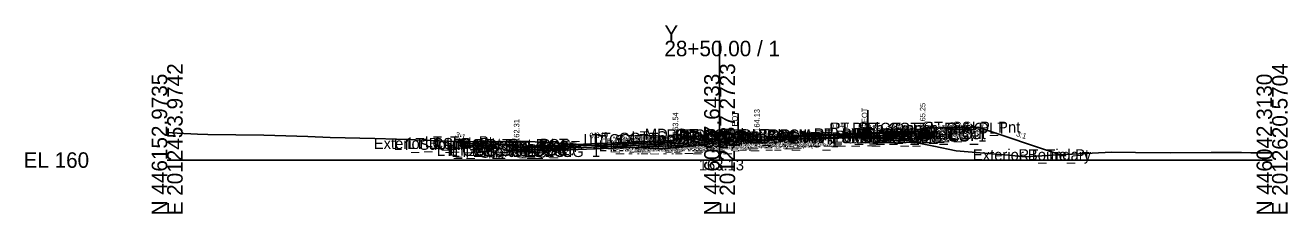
# Model space of a CAD drawing. Extents: x -26 to 3203, y -10 to 9532.
# Drawn here: x 1974.3 to 2202.8, y 2490.3 to 2524.4 of the extents above; entities that cross this region are included whole.
import ezdxf

# ---------------------------------------------------------------- set-up
doc = ezdxf.new("R2010")
doc.units = 0
for name, color, linetype in [('Default', 7, 'Continuous'), ('Exist CMT Pavement', 7, 'Continuous'), ('Exist Cross Section Cell', 7, 'Continuous'), ('Exist XS Center Line Elevation Label', 7, 'Continuous'), ('Exist XS Ground Line', 7, 'Continuous'), ('Prop CMT Conc Surface', 7, 'Continuous'), ('Prop CMT Concrete Structures', 7, 'Continuous'), ('Prop CMT Pvmt Course 1', 7, 'Continuous'), ('Prop CMT Pvmt Course 1 CG', 7, 'Continuous'), ('Prop CMT Pvmt Course 2', 7, 'Continuous'), ('Prop CMT Pvmt Course 2 Wedge', 7, 'Continuous'), ('Prop CMT Pvmt Course 3', 7, 'Continuous'), ('Prop CMT Pvmt Course 3 Wedge', 7, 'Continuous'), ('Prop CMT Pvmt Surface', 7, 'Continuous'), ('Prop CMT Slope Grass', 7, 'Continuous'), ('Prop CMT Subgrade Earthwork', 7, 'Continuous'), ('Prop XS Hydro Elevations', 7, 'Continuous'), ('Prop XS Label Text', 7, 'Continuous'), ('Prop XS SE Text', 7, 'Continuous'), ('Prop XS Side Slope Text', 7, 'Continuous'), ('Scratch_Level_0', 7, 'Continuous')]:
    doc.layers.add(name, color=color, linetype=linetype)

msp = doc.modelspace()

# ---------------------------------------------------------------- linework, layer by layer
at = {"layer": 'Exist CMT Pavement'}
msp.add_lwpolyline([(2103.35, 2503.42), (2103.35, 2503.42), (2104.94, 2503.48), (2105.71, 2503.51), (2107.81, 2503.59), (2109.14, 2503.64), (2111.71, 2503.73), (2112.49, 2503.75), (2113.7, 2503.79), (2114.54, 2503.83), (2115.17, 2503.85), (2117, 2503.89), (2117.68, 2503.9), (2118.22, 2503.92), (2120.67, 2503.97), (2121.48, 2503.99), (2122.74, 2504), (2123.31, 2504), (2123.68, 2504), (2125.46, 2504.03), (2126.84, 2504.04), (2126.84, 2504.04)], dxfattribs=at)
at = {"layer": 'Exist Cross Section Cell'}
for p, q in [((2100, 2500), (2100, 2521.56)), ((2000, 2500), (2100, 2500)), ((2100, 2500), (2200, 2500))]:
    msp.add_line(p, q, dxfattribs=at)
at = {"layer": 'Exist XS Ground Line'}
msp.add_lwpolyline([(2000, 2504.96), (2001.81, 2504.87), (2005.51, 2504.69), (2007.38, 2504.64), (2017.52, 2504.51), (2025.46, 2504.25), (2029.52, 2504.09), (2037.57, 2503.88), (2041.53, 2503.75), (2043.53, 2503.7), (2053.54, 2503.3), (2061.61, 2503.35), (2063.97, 2503.42), (2065.64, 2503.33), (2078.38, 2502.6), (2088.26, 2502.08), (2089.3, 2502.01), (2089.76, 2502.05), (2095.32, 2502.6), (2095.88, 2502.67), (2100, 2503.13), (2101.95, 2503.35), (2103.35, 2503.42), (2104.94, 2503.48), (2105.71, 2503.51), (2107.81, 2503.59), (2109.14, 2503.64), (2111.71, 2503.73), (2112.49, 2503.75), (2113.7, 2503.79), (2114.54, 2503.83), (2115.17, 2503.85), (2117, 2503.89), (2117.68, 2503.9), (2118.22, 2503.92), (2120.67, 2503.97), (2121.48, 2503.99), (2122.74, 2504), (2123.31, 2504), (2123.68, 2504), (2125.46, 2504.03), (2126.84, 2504.04), (2127.78, 2504.02), (2130.26, 2503.94), (2132.22, 2503.84), (2138.76, 2502.5), (2142.83, 2501.69), (2152.28, 2500.89), (2155.37, 2500.61), (2160.23, 2500.88), (2171.01, 2501.45), (2175.28, 2501.36), (2181.56, 2501.28), (2188.99, 2501.37), (2194.48, 2501.34), (2196.18, 2501.32), (2200, 2501.29)], dxfattribs=at)
at = {"layer": 'Prop CMT Conc Surface'}
for points in [[(2134.75, 2505.25), (2136.75, 2505.25)], [(2136.75, 2505.25), (2136.75, 2505.75), (2137.25, 2505.75)], [(2141.25, 2505.84), (2146.25, 2505.94)], [(2058.75, 2502.9), (2053.75, 2503)], [(2063.25, 2502.31), (2063.25, 2502.81), (2062.75, 2502.81)], [(2065.25, 2502.47), (2063.25, 2502.31)], [(2091.25, 2503.51), (2092, 2503.54), (2092, 2503.7), (2092.76, 2503.95)], [(2108.75, 2504.21), (2106.75, 2504.13), (2106.75, 2504.29), (2106, 2504.54)]]:
    msp.add_lwpolyline(points, dxfattribs=at)
at = {"layer": 'Prop CMT Concrete Structures'}
for points in [[(2134.75, 2505.25), (2136.75, 2505.25), (2136.75, 2505.75), (2137.25, 2505.75)], [(2137.25, 2505.75), (2137.25, 2504.76), (2134.75, 2504.66)], [(2134.75, 2504.66), (2134.75, 2505.25)], [(2146.25, 2505.94), (2141.25, 2505.84)], [(2141.25, 2505.84), (2141.25, 2505.5)], [(2141.25, 2505.5), (2146.25, 2505.6)], [(2146.25, 2505.6), (2146.25, 2505.94)], [(2053.75, 2502.66), (2053.75, 2503)], [(2053.75, 2503), (2058.75, 2502.9)], [(2058.75, 2502.56), (2053.75, 2502.66)], [(2058.75, 2502.9), (2058.75, 2502.56)], [(2065.25, 2502.47), (2063.25, 2502.31), (2063.25, 2502.81), (2062.75, 2502.81)], [(2062.75, 2502.81), (2062.75, 2501.78), (2065.25, 2501.88)], [(2065.25, 2501.88), (2065.25, 2502.47)], [(2091.25, 2503.51), (2092, 2503.54), (2092, 2503.7), (2092.76, 2503.95)], [(2091.25, 2502.92), (2091.25, 2503.51)], [(2092.76, 2502.98), (2091.25, 2502.92)], [(2092.76, 2503.95), (2092.76, 2502.98)], [(2108.75, 2504.21), (2106.75, 2504.13), (2106.75, 2504.29), (2106, 2504.54)], [(2106, 2504.54), (2106, 2503.51)], [(2106, 2503.51), (2108.75, 2503.62)], [(2108.75, 2503.62), (2108.75, 2504.21)]]:
    msp.add_lwpolyline(points, dxfattribs=at)
at = {"layer": 'Prop CMT Pvmt Course 1'}
for points in [[(2108.75, 2504.21), (2134.75, 2505.25)], [(2134.75, 2505), (2127.78, 2504.72), (2108.75, 2503.96)], [(2134.75, 2505.25), (2134.75, 2505)], [(2091.25, 2503.51), (2065.25, 2502.47)], [(2065.25, 2502.22), (2091.25, 2503.26)], [(2065.25, 2502.47), (2065.25, 2502.22)], [(2091.25, 2503.26), (2091.25, 2503.51)], [(2091.25, 2503.26), (2091.25, 2503.26), (2091.25, 2503.26)], [(2108.75, 2503.96), (2108.75, 2504.21)], [(2108.75, 2503.96), (2108.75, 2503.96)]]:
    msp.add_lwpolyline(points, dxfattribs=at)
at = {"layer": 'Prop CMT Pvmt Course 1 CG'}
for points in [[(2134.75, 2504.66), (2137.75, 2504.78), (2138.07, 2504.46)], [(2091.25, 2502.92), (2093.26, 2503), (2093.58, 2502.68)], [(2091.25, 2502.59), (2091.25, 2502.92)], [(2093.58, 2502.68), (2091.25, 2502.59)], [(2108.75, 2503.62), (2105.5, 2503.49), (2105.15, 2503.15)], [(2105.15, 2503.15), (2108.75, 2503.29)], [(2108.75, 2503.29), (2108.75, 2503.62)], [(2134.75, 2504.33), (2134.75, 2504.66)], [(2138.07, 2504.46), (2134.75, 2504.33)], [(2065.25, 2501.88), (2062.25, 2501.76), (2061.9, 2501.42)], [(2061.9, 2501.42), (2065.25, 2501.55)], [(2065.25, 2501.55), (2065.25, 2501.88)]]:
    msp.add_lwpolyline(points, dxfattribs=at)
at = {"layer": 'Prop CMT Pvmt Course 2'}
for points in [[(2126.84, 2504.68), (2134.75, 2505)], [(2134.75, 2505), (2134.75, 2504.66)], [(2091.25, 2503.26), (2065.25, 2502.22)], [(2065.25, 2501.88), (2091.25, 2502.92)], [(2091.25, 2502.92), (2091.25, 2503.26)], [(2108.75, 2503.96), (2108.75, 2503.96)], [(2126.84, 2504.35), (2126.84, 2504.68)], [(2134.75, 2504.66), (2126.84, 2504.35)], [(2065.25, 2502.22), (2065.25, 2501.88)]]:
    msp.add_lwpolyline(points, dxfattribs=at)
msp.add_lwpolyline([(2108.75, 2503.96), (2108.75, 2503.62), (2108.75, 2503.62)], close=True, dxfattribs=at)
at = {"layer": 'Prop CMT Pvmt Course 2 Wedge'}
msp.add_lwpolyline([(2108.75, 2503.96), (2126.84, 2504.68)], dxfattribs=at)
at = {"layer": 'Prop CMT Pvmt Course 3'}
for points in [[(2091.25, 2502.92), (2065.25, 2501.88)], [(2065.25, 2501.55), (2091.25, 2502.59)], [(2091.25, 2502.59), (2091.25, 2502.92)], [(2108.75, 2503.62), (2108.75, 2503.62), (2108.75, 2503.29), (2108.75, 2503.29)], [(2108.75, 2503.29), (2108.75, 2503.62)], [(2126.84, 2504.35), (2134.75, 2504.66)], [(2126.84, 2504.01), (2126.84, 2504.35)], [(2134.75, 2504.33), (2126.84, 2504.01)], [(2134.75, 2504.66), (2134.75, 2504.33)], [(2065.25, 2501.88), (2065.25, 2501.55)]]:
    msp.add_lwpolyline(points, dxfattribs=at)
at = {"layer": 'Prop CMT Pvmt Course 3 Wedge'}
msp.add_lwpolyline([(2108.75, 2503.62), (2126.84, 2504.35)], dxfattribs=at)
at = {"layer": 'Prop CMT Pvmt Surface'}
for points in [[(2108.75, 2504.21), (2134.75, 2505.25)], [(2091.25, 2503.51), (2065.25, 2502.47)]]:
    msp.add_lwpolyline(points, dxfattribs=at)
at = {"layer": 'Prop CMT Slope Grass'}
for points in [[(2137.25, 2505.75), (2146.75, 2505.94)], [(2146.75, 2505.94), (2161.7, 2500.95)], [(2053.25, 2503), (2052.19, 2503.35)], [(2062.75, 2502.81), (2053.25, 2503)], [(2092.76, 2503.95), (2099.38, 2504.68)], [(2106, 2504.54), (2099.38, 2504.68)]]:
    msp.add_lwpolyline(points, dxfattribs=at)
at = {"layer": 'Prop CMT Subgrade Earthwork'}
for points in [[(2134.75, 2504.33), (2138.07, 2504.46), (2139.4, 2505.79)], [(2065.25, 2501.55), (2061.9, 2501.42), (2060.47, 2502.85)], [(2091.25, 2502.59), (2065.25, 2501.55)], [(2093.58, 2502.68), (2091.25, 2502.59)], [(2091.25, 2502.59), (2091.25, 2502.59)], [(2091.25, 2502.59), (2091.25, 2502.59)], [(2095.11, 2504.21), (2093.58, 2502.68)], [(2103.71, 2504.59), (2105.15, 2503.15)], [(2105.15, 2503.15), (2108.75, 2503.29)], [(2108.75, 2503.29), (2108.74, 2503.63)], [(2108.75, 2503.29), (2108.75, 2503.29)], [(2108.75, 2503.29), (2108.75, 2503.29)], [(2126.83, 2504.04), (2126.84, 2504.01)], [(2126.84, 2504.01), (2134.75, 2504.33)], [(2134.75, 2504.33), (2134.75, 2504.33)], [(2065.25, 2501.55), (2065.25, 2501.55)]]:
    msp.add_lwpolyline(points, dxfattribs=at)
at = {"layer": 'Prop XS Label Text'}
for p, q in [((2103.35, 2508.42), (2103.35, 2503.42)), ((2126.84, 2509.04), (2126.84, 2504.04))]:
    msp.add_line(p, q, dxfattribs=at)

# ---------------------------------------------------------------- texts
at = {"layer": 'Default'}
msp.add_text('-', height=0.0001, dxfattribs=at).set_placement((2000, 2500))
at = {"layer": 'Exist Cross Section Cell'}
for s, p in [('Y', (2090, 2521.56)), ('28+50.00 / 1', (2090, 2518.76)), ('EL 160', (1974, 2498.6))]:
    msp.add_text(s, height=2.8, dxfattribs=at).set_placement(p)
for s, p in [('E 2012453.9742', (2002.8, 2490)), ('E 2012537.2723', (2102.8, 2490)), ('E 2012620.5704', (2202.8, 2490)), ('N 446152.9735', (2000, 2490)), ('N 446097.6433', (2100, 2490)), ('N 446042.3130', (2200, 2490))]:
    msp.add_text(s, height=2.8, rotation=90, dxfattribs=at).set_placement(p)
at = {"layer": 'Exist XS Center Line Elevation Label'}
msp.add_text('163.13', height=2, dxfattribs=at).set_placement((2096.23, 2498.13))
at = {"layer": 'Prop XS Hydro Elevations'}
for s, p in [('165.25', (2137.25, 2506.25)), ('162.31', (2063.75, 2503.31)), ('163.54', (2092.5, 2504.54)), ('164.13', (2107.25, 2505.13))]:
    msp.add_text(s, height=1, rotation=90, dxfattribs=at).set_placement(p)
at = {"layer": 'Prop XS Label Text'}
for p in [(2126.74, 2505.07), (2103.25, 2504.44)]:
    msp.add_text('E. EOT', height=1, rotation=90, dxfattribs=at).set_placement(p)
at = {"layer": 'Prop XS SE Text'}
for p in [(2076.46, 2503.92), (2119.96, 2505.66)]:
    msp.add_text('0.040', height=1, rotation=2.2906, dxfattribs=at).set_placement(p)
at = {"layer": 'Prop XS Side Slope Text'}
for p in [(2052.06, 2504.18), (2153.6, 2504.36)]:
    msp.add_text('3:1', height=1, rotation=341.5651, dxfattribs=at).set_placement(p)
at = {"layer": 'Scratch_Level_0'}
for s, p in [('LT_CG_Top_Face_Med', (2075.37, 2502.7)), ('LT_CG_Top_BOC_Med', (2077.15, 2502.95)), ('LT_Sub_DLT_In', (2084.05, 2503.21)), ('MD_Crown Point', (2086.45, 2503.68)), ('RT_CG_Top_BOC_Med', (2090.35, 2503.54)), ('RT_CG_Top_BOC In', (2091.97, 2503.54)), ('RT_Sub_DLT_In', (2092.61, 2503.59)), ('RT_CG_Top FOC In', (2092.61, 2503.29)), ('RT_CG_Top_Gut In', (2092.64, 2503.13)), ('RT_CG_Bot_IE_Med', (2094.77, 2502.62)), ('RT_PV_Sub_Tie_In', (2095.25, 2502.63)), ('RT_PV2_IEEOP', (2098.66, 2502.96)), ('RT_PV2_PGL', (2099.92, 2502.96)), ('RT_PV1_PGL', (2100.48, 2503.21)), ('RT_PV_Sub_Tie_Out', (2112.69, 2503.02)), ('RT_PV_OEEOP_EG', (2115.28, 2503.02)), ('RT_Sub_OEEOP', (2116.95, 2503.05)), ('RT_PV2_OEEOP', (2117.04, 2503.72)), ('RT_PV3_OEEOP', (2117.04, 2503.39)), ('RT_Sub_Trench_Out_DLT', (2119.92, 2504.79)), ('RT_Sub_OEOT_CG_1', (2120.92, 2503.33)), ('RT_CG_Top_Face', (2123.96, 2504.75)), ('RT_CG1_Shelf_Out', (2124.25, 2503.78)), ('RT_CG_Bot_IE', (2124.62, 2503.66)), ('RT_Sub_OEOT', (2124.78, 2503.33)), ('RT_PV2_OEOT', (2124.88, 2504)), ('RT_PV3_OEOT', (2124.88, 2503.66)), ('RT_CG_Top_Gut', (2124.94, 2504.25)), ('RT_PV1_OEOT', (2125.44, 2504.25)), ('RT_CG_Top_BOC', (2125.49, 2504.75)), ('RT_CG_Bot_BOC', (2125.52, 2503.76)), ('RT_Sub_OEOP', (2128.13, 2503.46)), ('RT_CSLP_Pnt', (2136.88, 2504.94)), ('Exterior Boundary', (2037.39, 2502)), ('LT_Sub_Trench_Out_DLT', (2041.03, 2501.85)), ('LT_CSLP_Pnt', (2043.42, 2502)), ('LT_Tie_Pt', (2046.6, 2502.3)), ('LT_CG1_Shelf_Out', (2048.8, 2500.76)), ('LT_CG_Top_Face', (2050.51, 2501.81)), ('LT_CG_Top_BOC', (2051.03, 2501.81)), ('LT_CG_Bot_BOC', (2051.06, 2500.78)), ('LT_Sub_OEOT_CG_1', (2051.47, 2500.55)), ('LT_CG_Top_Gut', (2051.49, 2501.31)), ('LT_Sub_OEOP', (2052.01, 2500.42)), ('LT_CG_Bot_IE', (2055.16, 2500.88)), ('LT_Sub_OEOT', (2055.33, 2500.55)), ('LT_PV2_OEOT', (2055.42, 2501.22)), ('LT_PV3_OEOT', (2055.42, 2500.88)), ('LT_PV1_OEOT', (2055.99, 2501.47)), ('LT_CG_Top_Gut_Med', (2076.35, 2502.54)), ('LT_CG_Bot_BOC_Med', (2077.19, 2501.98)), ('LT_CG_Bot_IE_Med', (2077.31, 2501.92)), ('LT_Sub_IEOT_CG_1', (2078.12, 2501.59)), ('LT_Sub_OEEOP', (2080.46, 2501.59)), ('LT_PV2_OEEOP', (2080.56, 2502.26)), ('LT_PV3_OEEOP', (2080.56, 2501.92)), ('LT_Sub_IEEOP', (2081.11, 2501.59)), ('LT_PV2_IEEOP', (2081.2, 2502.26)), ('LT_CG1_Shelf_In', (2081.43, 2502)), ('LT_Sub_PGL', (2082.37, 2501.59)), ('LT_PV2_PGL', (2082.46, 2502.26)), ('LT_PV1_PGL', (2083.03, 2502.51)), ('LT_Sub_IEOP', (2084.34, 2501.68)), ('RT_CG_Bot BOC In', (2091.84, 2502.51)), ('RT_CG1_Shelf_In', (2093.63, 2502.49)), ('RT_Sub_IEOT_CG_1', (2095.57, 2502.29)), ('RT_Sub_IEOP', (2095.86, 2502.15)), ('RT_PV_IEEOP_EG', (2096.89, 2502.63)), ('RT_Sub_IEEOP', (2098.56, 2502.29)), ('RT_PV3_IEEOP', (2098.66, 2502.62)), ('RT_Sub_PGL', (2099.82, 2502.29)), ('RT_PV3_PGL', (2099.92, 2502.62)), ('Exterior Boundary', (2145.84, 2499.95)), ('RT_Tie_Pt', (2154.1, 2499.95))]:
    msp.add_text(s, height=2, dxfattribs=at).set_placement(p)

doc.saveas('drawing.dxf')
